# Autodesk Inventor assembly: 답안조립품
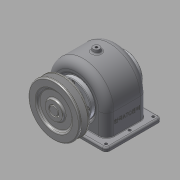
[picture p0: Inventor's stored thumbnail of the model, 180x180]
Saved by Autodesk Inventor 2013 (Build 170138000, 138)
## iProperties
Created: 2015-09
Part Number: 답안조립품
Document SubType Name: Assembly
Designer: Administrator
Author: Administrator
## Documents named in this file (14)
- C:\Users\Administrator\Desktop\450908V1009\답안조립품.iam
- C:\Users\Administrator\Desktop\450908V1009\본체.ipt
- C:\Users\Administrator\Desktop\450908V1009\V-벨트풀리.ipt
- C:\Users\Administrator\Desktop\450908V1009\뒤커버.ipt
- C:\Users\Administrator\Desktop\450908V1009\멈춤나사 - M4x10.ipt
- C:\Users\Administrator\Desktop\450908V1009\베어링 6203.ipt
- C:\Users\Administrator\Desktop\450908V1009\볼트 M3 x 8.ipt
- C:\Users\Administrator\Desktop\450908V1009\볼트 M3 x 10.ipt
- C:\Users\Administrator\Desktop\450908V1009\스퍼기어.ipt
- C:\Users\Administrator\Desktop\450908V1009\앞커버.ipt
- C:\Users\Administrator\Desktop\450908V1009\오일 실 17 32 8.ipt
- C:\Users\Administrator\Desktop\450908V1009\축.ipt
- C:\Users\Administrator\Desktop\450908V1009\키 - 5 x 5 x 18.ipt
- C:\Users\Administrator\Desktop\450908V1009\키 - 6 x 6 x 22.ipt
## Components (9 placed, 3 different names)
1. V-벨트풀리:1 — 플러쉬:1, 각도:3
2. ISO 4762 M3 x 10:1
3. ISO 4762 M3 x 10:2
4. ISO 4762 M3 x 10:3
5. ISO 4762 M3 x 10:4
6. ISO 4762 M3 x 8:1
7. ISO 4762 M3 x 8:2
8. ISO 4762 M3 x 8:3
9. ISO 4762 M3 x 8:4
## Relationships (2: Flush 1, Angle 1)
- 플러쉬:1 [Flush]: V-벨트풀리:1
- 각도:3 [Angle]: V-벨트풀리:1
